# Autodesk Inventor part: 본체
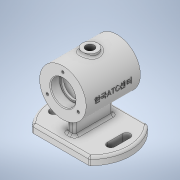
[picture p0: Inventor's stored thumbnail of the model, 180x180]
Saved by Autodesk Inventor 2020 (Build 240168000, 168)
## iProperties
Created: 2021-09
Part Number: 본체
Material: 일반
Document SubType Name: Modeling
Designer: Administrator
Density: 1 g/cm^3
Appearance: 기본값
Author: Administrator
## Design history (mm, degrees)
sketch "스케치1"
  geometry: L1 (-37.5, -36.742)-(-37.5, 36.742); L2 (37.5, 36.742)-(37.5, -36.742); A1 r 52.5 centre (0, 0) between (-37.5, -36.742) and (-37.5, 36.742); 1 further point
  constraints: 4 end point, 4 point on circle, 2 vertical, 1 centre point, 1 coincident
  dimensions: "d0" = 105 diameter of A1; "d1" = 75 distance between parallel lines of L2 L1; "d2" = 37.5 distance from line of point (0, 0) L2 (= 0.5 x d1)
extrude "돌출1" new body sketch "스케치1" distance "d3" = 10; taper "d4" = 0 deg
sketch "스케치2"
  geometry: L1 (36.742, 0)-(-36.742, 0) reference; C1 r 30 at (0, 62); 2 further points
  constraints: 1 centre point, 1 midpoint, 1 vertical alignment
  dimensions: "d5" = 62 distance from line of L1 C1.centre; "d6" = 60 diameter of C1
extrude "돌출2" join sketch "스케치2" stored distance "d7" = 70; taper "d8" = 0 deg
node "작업 평면1"
sketch "스케치3"
  geometry: C1 r 10 at (0, 0); 1 further point
  constraints: 1 centre point, 1 coincident
  dimensions: "d10" = 20 diameter of C1
extrude "돌출3" join sketch "스케치3" stored distance "d11" = 70; taper "d12" = 0 deg
sketch "스케치4"
  geometry: L1 (-25, 3.472)-(25, 3.472); L2 (25, 3.472)-(25, 64.583); L3 (25, 64.583)-(-25, 64.583); L4 (-25, 64.583)-(-25, 3.472); L5 (-25, 3.472)-(25, 64.583); L6 (25, 3.472)-(-25, 64.583); 3 further points
  constraints: 12 end point, 3 midpoint, 2 parallel, 1 horizontal, 1 perpendicular, 1 vertical alignment
  dimensions: "d13" = 50 distance of L1.start L1.end
extrude "돌출4" join sketch "스케치4" stored distance "d14" = 10; taper "d15" = 0 deg
sketch "스케치5"
  geometry: L1 (-10, 37)-(10, 37); L2 (-10, 32)-(10, 32); L3 (10, 42)-(-10, 42); A1 r 5 centre (-10, 37) between (-10, 42) and (-10, 32); A2 r 5 centre (10, 37) between (10, 32) and (10, 42); 2 further points
  constraints: 8 end point, 4 point on circle, 4 tangent, 2 centre point, 1 horizontal, 1 midpoint, 1 parallel, 1 vertical alignment
  dimensions: "d16" = 5 radius of A2; "d17" = 37 distance from line of point (0, 0) L1; "d18" = 20 distance of L1.start L1.end
extrude "돌출5" cut sketch "스케치5" extent not by distance; stored distance "d19" = 0; taper "d20" = 0 deg
sketch "스케치6"
  geometry: C1 r 10 at (0, 0) reference; 2 further points
  constraints: 1 coincident
hole "구멍1" sketch "스케치6" at (0, 0) diameter "d21" = 10.917; stored, may be unused: countersink angle "d25" = 90 deg, drill point angle "d27" = 118 deg; dims "d22" = 24, "d23" = 4, "d24" = 2, "d26" = 29.1
sketch "스케치7"
  geometry: L1 (35, 32)-(35, 92) reference; L2 (35, 62)-(-89.458, 62); L3 (35, 78)-(23, 78); L4 (23, 78)-(23, 76); L5 (23, 76)-(20, 76); L6 (20, 76)-(20, 87); L7 (20, 87)-(-20, 87); L8 (-20, 87)-(-20, 76); L9 (-20, 76)-(-23, 76); L10 (-23, 76)-(-23, 78); L11 (-23, 78)-(-35, 78); L12 (-35, 92)-(-35, 32) reference; 2 further points
  constraints: 20 end point, 6 perpendicular, 5 point on line, 2 horizontal, 1 midpoint
  dimensions: "d28" = 50 diameter of L7 L2; "d29" = 28 diameter of L5 L2; "d30" = 32 diameter of L3 L2; "d31" = 12 distance of L3.start L3.end; "d32" = 12 distance of L10.end L11.end (= d31); "d33" = 40 distance of L6.end L7.end; "d34" = 3 distance of L4.end L5.end; "d35" = 3 distance of L8.end L9.end
revolve "회전1" sketch "스케치7" stored, may be unused: angle "d36" = 90 deg
sketch "스케치8"
  geometry: C1 r 16 at (0, 0) reference; 2 further points
  constraints: 1 horizontal alignment
  dimensions: "d37" = 23 distance of point (-23, 0) C1.centre
hole "구멍2" sketch "스케치8" at (-23, 0) diameter "d38" = 3.242; stored, may be unused: countersink angle "d42" = 90 deg, drill point angle "d44" = 118 deg; dims "d39" = 8, "d40" = 4, "d41" = 2, "d43" = 10
fillet "모깎기1" dims "d48" = 0.3, "d49" = 3
fillet "모깎기2" dims "d50" = 3
chamfer "모따기1" distance "d51" = 1; stored, may be unused: second distance "d52" = 2, angle "d53" = 45 deg
node "작업 평면3"
  node "작업 평면2"
sketch "스케치9"
  geometry: L1 (-35, 30)-(-35, -30) reference; L2 (-35, 30)-(35, 30) reference; 2 further points
  constraints: 1 other
  dimensions: "d55" = 35 distance from line of L1 point (0, 0); "d56" = 30 distance from line of L2 point (0, 0)
feature "엠보싱1" sketch "스케치9" dims "d0" = 105, "d1" = 75, "d2" = 37.5 (= 0.5 x d1), "d13" = 50, "d57" = 0.5, "d58" = 0
node "솔리드1"
mirror "미러1"
pattern_circular "원형 패턴1" dims angle "d46" = 360 deg
mirror "미러2"
feature "A9D066F2-1C7D-4E18-AEED-F7BC21143FA4" dims "d21" = 10.917, "d22" = 24, "d23" = 4, "d24" = 2, "d25" = 90 deg, "d26" = 29.1, "d27" = 118 deg
other parameters: "d9" = 95
